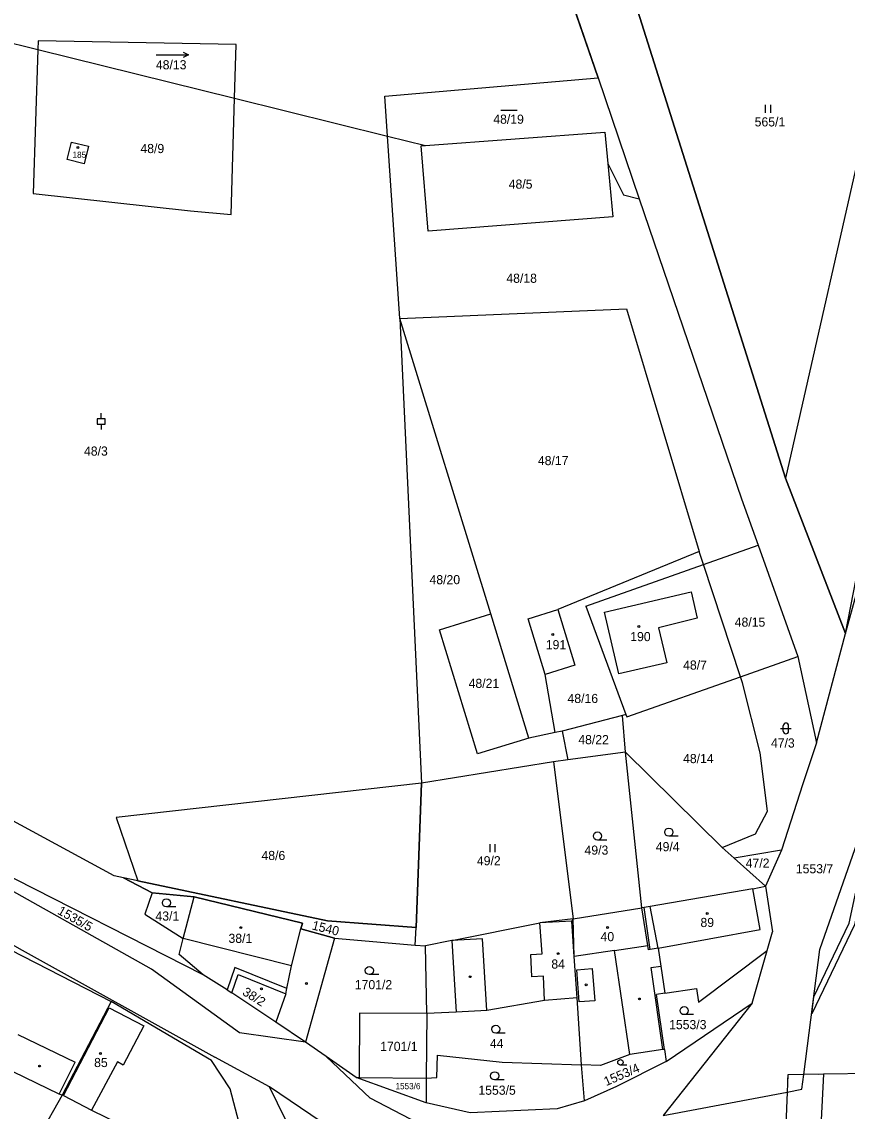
# Model space of a CAD drawing. Extents: x -801826 to -800592, y -1032871 to -1031813.
# Drawn here: x -801124.4 to -800970.8, y -1032380.8 to -1032178.1 of the extents above; entities that cross this region are included whole.
import ezdxf

# ---------------------------------------------------------------- set-up
doc = ezdxf.new("R2010")
doc.units = 0
for name, color, linetype in [('Vrstva 1', 7, 'Continuous'), ('Vrstva 18', 7, 'Continuous'), ('Vrstva 19', 7, 'Continuous'), ('Vrstva 25', 7, 'Continuous'), ('Vrstva 26', 7, 'Continuous'), ('Vrstva 27', 7, 'Continuous'), ('Vrstva 4', 7, 'Continuous')]:
    doc.layers.add(name, color=color, linetype=linetype)

msp = doc.modelspace()

# ---------------------------------------------------------------- linework, layer by layer
at = {"layer": 'Vrstva 1'}
for p, q in [((-801013.92, -1032163.13), (-800982.29, -1032263)), ((-800982.29, -1032263), (-801013.92, -1032163.13)), ((-801017.21, -1032188.54), (-801025.45, -1032164.36)), ((-801025.45, -1032164.36), (-801017.21, -1032188.54)), ((-800962.57, -1032175.77), (-800982.29, -1032263)), ((-801137.55, -1032179.29), (-801121.44, -1032183.28)), ((-801121.44, -1032183.28), (-801122.3, -1032210.08)), ((-801121.39, -1032181.67), (-801121.44, -1032183.28)), ((-801121.44, -1032183.28), (-801084.84, -1032192.36)), ((-801084.53, -1032182.36), (-801121.39, -1032181.67)), ((-801084.84, -1032192.36), (-801084.53, -1032182.36)), ((-800971.16, -1032291.94), (-800949.8, -1032181.86)), ((-801056.9, -1032191.96), (-801017.21, -1032188.54)), ((-801017.21, -1032188.54), (-801009.54, -1032211.04)), ((-801017.21, -1032188.54), (-801009.54, -1032211.04)), ((-801085.5, -1032214.01), (-801084.84, -1032192.36)), ((-801084.84, -1032192.36), (-801056.39, -1032199.42)), ((-801056.39, -1032199.42), (-801056.9, -1032191.96)), ((-801056.39, -1032199.42), (-801049.32, -1032201.17)), ((-801054.08, -1032233.3), (-801056.39, -1032199.42)), ((-801049.32, -1032201.17), (-801015.96, -1032198.66)), ((-801015.96, -1032198.66), (-801015.4, -1032204.5)), ((-801115.98, -1032203.74), (-801115.19, -1032200.51)), ((-801115.19, -1032200.51), (-801112.05, -1032201.3)), ((-801112.05, -1032201.3), (-801112.85, -1032204.53)), ((-801050.11, -1032201.23), (-801049.32, -1032201.17)), ((-801048.82, -1032217.11), (-801050.11, -1032201.23)), ((-801112.85, -1032204.53), (-801115.98, -1032203.74)), ((-801015.4, -1032204.5), (-801014.44, -1032214.44)), ((-801015.4, -1032204.5), (-801012.5, -1032210.33)), ((-801122.3, -1032210.08), (-801093.06, -1032213.29)), ((-801012.5, -1032210.33), (-801009.54, -1032211.04)), ((-801009.54, -1032211.04), (-800990.52, -1032266.86)), ((-801009.54, -1032211.04), (-800990.52, -1032266.86)), ((-801093.06, -1032213.29), (-801085.5, -1032214.01)), ((-801014.44, -1032214.44), (-801048.82, -1032217.11)), ((-801054.08, -1032233.3), (-801011.88, -1032231.52)), ((-801011.88, -1032231.52), (-800998.39, -1032276.7)), ((-801037.18, -1032288.28), (-801054.08, -1032233.3)), ((-801054.08, -1032233.3), (-801050.04, -1032319.76)), ((-800971.16, -1032291.94), (-800962.88, -1032261.83)), ((-800982.29, -1032263), (-800971.16, -1032291.94)), ((-800971.16, -1032291.94), (-800982.29, -1032263)), ((-800990.52, -1032266.86), (-800987.43, -1032275.48)), ((-800990.52, -1032266.86), (-800987.43, -1032275.48)), ((-800998.39, -1032276.7), (-801024.68, -1032287.48)), ((-800997.6, -1032279.08), (-800998.39, -1032276.7)), ((-800997.6, -1032279.08), (-800987.43, -1032275.48)), ((-800987.43, -1032275.48), (-800980, -1032296.19)), ((-800987.43, -1032275.48), (-800980, -1032296.19)), ((-801019.47, -1032286.83), (-800997.6, -1032279.08)), ((-800990.69, -1032299.97), (-800997.6, -1032279.08)), ((-801016.02, -1032287.95), (-800999.9, -1032284.18)), ((-800999.9, -1032284.18), (-800998.75, -1032289.09)), ((-801019.47, -1032286.83), (-801012.02, -1032307.02)), ((-801046.72, -1032291.22), (-801037.18, -1032288.28)), ((-801030.07, -1032311.4), (-801037.18, -1032288.28)), ((-801030.24, -1032289.17), (-801024.68, -1032287.48)), ((-801024.68, -1032287.48), (-801021.55, -1032297.82)), ((-801013.33, -1032299.43), (-801016.02, -1032287.95)), ((-801027.03, -1032299.56), (-801030.24, -1032289.17)), ((-800998.75, -1032289.09), (-801005.96, -1032290.88)), ((-801005.96, -1032290.88), (-801004.43, -1032297.4)), ((-801039.62, -1032314.34), (-801046.72, -1032291.22)), ((-800976.55, -1032312.27), (-800971.16, -1032291.94)), ((-800976.55, -1032312.27), (-800971.16, -1032291.94)), ((-800990.69, -1032299.97), (-800980, -1032296.19)), ((-800980, -1032296.19), (-800976.55, -1032312.27)), ((-800980, -1032296.19), (-800976.55, -1032312.27)), ((-801021.55, -1032297.82), (-801027.03, -1032299.56)), ((-801004.43, -1032297.4), (-801013.33, -1032299.43)), ((-801025.17, -1032310.34), (-801027.03, -1032299.56)), ((-801011.85, -1032307.45), (-800990.69, -1032299.97)), ((-800990.31, -1032301.13), (-800990.69, -1032299.97)), ((-800987.03, -1032314.12), (-800990.31, -1032301.13)), ((-801012.02, -1032307.02), (-801012.66, -1032307.19)), ((-801012.02, -1032307.02), (-801011.85, -1032307.45)), ((-801012.66, -1032307.19), (-801023.91, -1032310.07)), ((-801012.07, -1032314.03), (-801012.66, -1032307.19)), ((-801025.17, -1032310.34), (-801030.07, -1032311.4)), ((-801023.91, -1032310.07), (-801025.17, -1032310.34)), ((-801023.91, -1032310.07), (-801022.81, -1032315.43)), ((-801107.26, -1032337.02), (-801154.2, -1032311.57)), ((-801030.07, -1032311.4), (-801039.62, -1032314.34)), ((-800976.55, -1032312.27), (-800979.08, -1032319.89)), ((-801012.07, -1032314.03), (-801022.81, -1032315.43)), ((-800994.1, -1032331.73), (-801012.07, -1032314.03)), ((-801009.04, -1032342.97), (-801012.07, -1032314.03)), ((-800985.64, -1032324.97), (-800987.03, -1032314.12)), ((-801025.49, -1032315.78), (-801050.04, -1032319.76)), ((-801022.81, -1032315.43), (-801025.49, -1032315.78)), ((-801025.49, -1032315.78), (-801021.83, -1032344.98)), ((-801090.72, -1032355.44), (-801158.69, -1032320.84)), ((-801050.04, -1032319.76), (-801106.91, -1032326.16)), ((-801050.04, -1032319.76), (-801106.91, -1032326.16)), ((-801050.04, -1032319.76), (-801051.08, -1032346.63)), ((-801051.08, -1032346.63), (-801050.04, -1032319.76)), ((-800979.08, -1032319.89), (-800983.07, -1032332.22)), ((-801100.28, -1032354.34), (-801156.42, -1032323.04)), ((-800987.89, -1032329.2), (-800985.64, -1032324.97)), ((-801106.91, -1032326.16), (-801102.87, -1032337.94)), ((-801106.91, -1032326.16), (-801102.87, -1032337.94)), ((-800975.92, -1032350.71), (-800967.6, -1032326.98)), ((-800994.1, -1032331.73), (-800987.89, -1032329.2)), ((-801156.86, -1032332.67), (-801124.35, -1032350.83)), ((-800994.1, -1032331.73), (-800991.87, -1032333.72)), ((-800983.07, -1032332.22), (-800991.87, -1032333.72)), ((-800983.07, -1032332.22), (-800986.02, -1032338.94)), ((-800991.87, -1032333.72), (-800986.02, -1032338.94)), ((-801105.53, -1032337.38), (-801107.26, -1032337.02)), ((-801102.87, -1032337.94), (-801105.53, -1032337.38)), ((-801100.21, -1032340.16), (-801105.53, -1032337.38)), ((-801102.87, -1032337.94), (-801105.53, -1032337.38)), ((-801105.53, -1032337.38), (-801100.21, -1032340.16)), ((-801067.58, -1032345.38), (-801102.87, -1032337.94)), ((-801102.87, -1032337.94), (-801067.58, -1032345.38)), ((-801067.58, -1032345.38), (-801102.87, -1032337.94)), ((-800988.43, -1032339.45), (-801007.51, -1032342.71)), ((-800988.43, -1032339.45), (-800986.02, -1032338.94)), ((-800986.02, -1032338.94), (-800984.74, -1032347.41)), ((-801100.21, -1032340.16), (-801101.56, -1032344.12)), ((-801092.35, -1032340.92), (-801100.21, -1032340.16)), ((-801100.21, -1032340.16), (-801092.35, -1032340.92)), ((-801094.39, -1032348.66), (-801092.35, -1032340.92)), ((-801072.22, -1032345.8), (-801092.35, -1032340.92)), ((-801092.35, -1032340.92), (-801072.22, -1032345.8)), ((-801021.83, -1032344.98), (-801009.04, -1032342.97)), ((-801008.64, -1032342.91), (-801009.04, -1032342.97)), ((-801007.51, -1032342.71), (-801008.64, -1032342.91)), ((-801007.52, -1032350.72), (-801008.64, -1032342.91)), ((-801101.56, -1032344.12), (-801094.39, -1032348.66)), ((-801051.08, -1032346.63), (-801067.58, -1032345.38)), ((-801067.58, -1032345.38), (-801051.08, -1032346.63)), ((-801051.08, -1032346.63), (-801067.58, -1032345.38)), ((-801021.83, -1032344.98), (-801028.02, -1032345.75)), ((-801022.11, -1032345.46), (-801021.83, -1032344.98)), ((-801021.64, -1032352.01), (-801022.11, -1032345.46)), ((-801072.52, -1032346.86), (-801072.22, -1032345.8)), ((-801072.22, -1032345.8), (-801072.52, -1032346.86)), ((-801066.26, -1032348.61), (-801072.52, -1032346.86)), ((-801072.52, -1032346.86), (-801066.26, -1032348.61)), ((-801051.21, -1032349.89), (-801051.08, -1032346.63)), ((-801051.21, -1032349.89), (-801051.08, -1032346.63)), ((-801044.4, -1032349.06), (-801028.02, -1032345.75)), ((-800985.74, -1032350.88), (-800984.74, -1032347.41)), ((-801131.91, -1032348.04), (-801107.8, -1032360.39)), ((-801095.18, -1032351.66), (-801094.39, -1032348.66)), ((-801066.26, -1032348.61), (-801071.67, -1032367.94)), ((-801066.26, -1032348.61), (-801051.21, -1032349.89)), ((-801066.26, -1032348.61), (-801051.21, -1032349.89)), ((-801044.4, -1032349.06), (-801049.3, -1032350.05)), ((-801124.35, -1032350.83), (-801088.51, -1032370.73)), ((-801090.72, -1032355.44), (-801095.18, -1032351.66)), ((-801051.21, -1032349.89), (-801049.3, -1032350.05)), ((-801049.09, -1032362.64), (-801049.3, -1032350.05)), ((-801006.04, -1032350.45), (-801007.52, -1032350.72)), ((-801006.04, -1032350.45), (-801005.53, -1032353.78)), ((-800998.5, -1032360.53), (-800985.74, -1032350.88)), ((-800988.54, -1032360.72), (-800985.74, -1032350.88)), ((-800978.9, -1032373.98), (-800975.92, -1032350.71)), ((-801021.08, -1032359.72), (-801021.64, -1032352.01)), ((-801005.53, -1032353.78), (-801004.75, -1032358.85)), ((-801083.91, -1032366.23), (-801100.28, -1032354.34)), ((-801086.23, -1032358.24), (-801090.72, -1032355.44)), ((-801084.78, -1032354.07), (-801086.23, -1032358.24)), ((-801075.14, -1032357.96), (-801084.78, -1032354.07)), ((-801086.23, -1032358.24), (-801085.38, -1032358.78)), ((-801077.2, -1032364.24), (-801085.38, -1032358.78)), ((-801075.31, -1032358.95), (-801077.2, -1032364.24)), ((-801075.31, -1032358.95), (-801075.14, -1032357.96)), ((-801021.08, -1032359.72), (-801027.16, -1032360.2)), ((-801020.27, -1032372.17), (-801021.08, -1032359.72)), ((-801004.75, -1032358.85), (-801006.32, -1032359.09)), ((-801004.85, -1032369.3), (-801006.32, -1032359.09)), ((-801004.75, -1032358.85), (-800998.87, -1032357.96)), ((-800998.87, -1032357.96), (-800998.5, -1032360.53)), ((-801107.8, -1032360.39), (-801116.96, -1032377.78)), ((-801089.14, -1032371.37), (-801107.8, -1032360.39)), ((-801027.16, -1032360.2), (-801037.91, -1032362.04)), ((-800988.54, -1032360.72), (-801005.11, -1032381.61)), ((-801004.53, -1032371.53), (-800988.54, -1032360.72)), ((-801061.59, -1032362.54), (-801061.68, -1032374.54)), ((-801049.09, -1032362.64), (-801061.59, -1032362.54)), ((-801049.09, -1032362.64), (-801049.18, -1032374.64)), ((-801043.6, -1032362.38), (-801049.09, -1032362.64)), ((-801037.91, -1032362.04), (-801043.6, -1032362.38)), ((-801071.67, -1032367.94), (-801077.2, -1032364.24)), ((-801071.67, -1032367.94), (-801083.91, -1032366.23)), ((-801067.79, -1032370.64), (-801071.67, -1032367.94)), ((-801005.15, -1032369.34), (-801011.28, -1032370.25)), ((-801004.85, -1032369.3), (-801005.15, -1032369.34)), ((-801004.85, -1032369.3), (-801004.53, -1032371.53)), ((-801085.69, -1032376.62), (-801089.14, -1032371.37)), ((-801078.35, -1032376.25), (-801088.51, -1032370.73)), ((-801062.22, -1032374.52), (-801067.79, -1032370.64)), ((-801059.61, -1032378.37), (-801067.79, -1032370.64)), ((-801047.18, -1032374.54), (-801047.08, -1032370.36)), ((-801047.08, -1032370.36), (-801035.07, -1032371.66)), ((-801035.07, -1032371.66), (-801020.27, -1032372.17)), ((-801011.28, -1032370.25), (-801016.75, -1032372.29)), ((-801004.53, -1032371.53), (-801013.78, -1032376.2)), ((-801117.49, -1032377.59), (-801128.07, -1032372.48)), ((-801019.72, -1032378.86), (-801020.27, -1032372.17)), ((-801016.75, -1032372.29), (-801020.27, -1032372.17)), ((-800979.26, -1032376.69), (-800978.9, -1032373.98)), ((-800975.27, -1032373.92), (-800978.9, -1032373.98)), ((-800945.84, -1032373.44), (-800975.27, -1032373.92)), ((-801049.22, -1032379.24), (-801062.22, -1032374.52)), ((-801062.22, -1032374.52), (-801061.68, -1032374.54)), ((-801061.68, -1032374.54), (-801049.18, -1032374.64)), ((-801049.18, -1032374.64), (-801049.22, -1032379.24)), ((-801049.18, -1032374.64), (-801047.18, -1032374.54)), ((-801116.96, -1032377.78), (-801126.31, -1032394.49)), ((-801116.96, -1032377.78), (-801117.49, -1032377.59)), ((-801116.7, -1032377.88), (-801116.96, -1032377.78)), ((-801116.7, -1032377.88), (-801111.48, -1032380.61)), ((-801082.53, -1032388.65), (-801085.69, -1032376.62)), ((-801061.11, -1032387.87), (-801078.35, -1032376.25)), ((-801072.24, -1032388.64), (-801078.35, -1032376.25)), ((-801013.78, -1032376.2), (-801019.72, -1032378.86)), ((-801005.11, -1032381.61), (-800982.02, -1032377.22)), ((-800982.02, -1032377.22), (-800979.26, -1032376.69)), ((-801043.92, -1032386.49), (-801059.61, -1032378.37)), ((-801041, -1032381.1), (-801049.22, -1032379.24)), ((-801019.72, -1032378.86), (-801024.79, -1032380.35)), ((-801111.48, -1032380.61), (-801105.99, -1032383.29)), ((-801024.79, -1032380.35), (-801041, -1032381.1))]:
    msp.add_line(p, q, dxfattribs=at)
at = {"layer": 'Vrstva 25'}
for p, q in [((-801099.42, -1032184.3), (-801093.42, -1032184.3)), ((-800986.11, -1032193.6), (-800986.11, -1032195.1)), ((-800985.08, -1032195.1), (-800985.08, -1032193.6)), ((-801035.28, -1032194.58), (-801032.28, -1032194.58)), ((-801109.68, -1032251.97), (-801109.68, -1032250.97)), ((-801109.68, -1032252.97), (-801109.68, -1032253.97)), ((-800982.74, -1032310.09), (-800982.74, -1032309.09)), ((-800981.74, -1032310.09), (-800981.74, -1032309.09)), ((-800983.24, -1032309.59), (-800981.24, -1032309.59)), ((-801037.37, -1032331.09), (-801037.37, -1032332.59)), ((-801036.34, -1032332.59), (-801036.34, -1032331.09)), ((-801015.57, -1032330.35), (-801017.32, -1032330.35)), ((-801002.28, -1032329.63), (-801004.03, -1032329.63)), ((-801095.78, -1032342.78), (-801097.53, -1032342.78)), ((-801058.02, -1032355.37), (-801059.77, -1032355.37)), ((-800999.44, -1032362.83), (-801001.19, -1032362.83)), ((-801034.49, -1032366.29), (-801036.24, -1032366.29)), ((-801011.87, -1032372.2), (-801013.04, -1032372.2)), ((-801034.7, -1032374.96), (-801036.45, -1032374.96))]:
    msp.add_line(p, q, dxfattribs=at)
msp.add_lwpolyline([(-801094.42, -1032183.8), (-801093.42, -1032184.3), (-801094.42, -1032184.8)], dxfattribs=at)
msp.add_lwpolyline([(-801110.43, -1032252.97), (-801108.93, -1032252.97), (-801108.93, -1032251.97), (-801110.43, -1032251.97)], close=True, dxfattribs=at)
for centre, radius in [((-801113.99, -1032201.53), 0.175), ((-801009.63, -1032290.61), 0.175), ((-801025.65, -1032292.12), 0.175), ((-801017.32, -1032329.6), 0.75), ((-801004.03, -1032328.88), 0.75), ((-801097.53, -1032342.03), 0.75), ((-800996.87, -1032344.03), 0.175), ((-801083.69, -1032346.64), 0.175), ((-801015.42, -1032346.62), 0.175), ((-801024.61, -1032351.48), 0.175), ((-801059.77, -1032354.62), 0.75), ((-801041.01, -1032355.77), 0.175), ((-801071.49, -1032357.04), 0.175), ((-801019.42, -1032357.3), 0.175), ((-801079.86, -1032358.03), 0.175), ((-801009.52, -1032359.91), 0.175), ((-801001.19, -1032362.08), 0.75), ((-801036.24, -1032365.54), 0.75), ((-801109.83, -1032370.07), 0.175), ((-801013.04, -1032371.7), 0.503), ((-801121.13, -1032372.38), 0.175), ((-801036.45, -1032374.21), 0.75)]:
    msp.add_circle(centre, radius, dxfattribs=at)
for centre, start, end in [((-800982.24, -1032309.09), 0, 180), ((-800982.24, -1032310.09), 180, 0)]:
    msp.add_arc(centre, 0.5, start, end, dxfattribs=at)
at = {"layer": 'Vrstva 26'}
for p, q in [((-800981.9, -1032374.03), (-800981.94, -1032375.03)), ((-800975.27, -1032373.92), (-800976.27, -1032373.94))]:
    msp.add_line(p, q, dxfattribs=at)
at = {"layer": 'Vrstva 27'}
msp.add_lwpolyline([(-800970.45, -1032345.79), (-800963.99, -1032315.79), (-800963.02, -1032316.04), (-800969.49, -1032346.11), (-800977.45, -1032362.66), (-800977.05, -1032359.51), (-800970.45, -1032345.79)], dxfattribs=at)
at = {"layer": 'Vrstva 4'}
for p, q in [((-800987.02, -1032346.96), (-800988.43, -1032339.45)), ((-801007.91, -1032349.96), (-801009.04, -1032342.97)), ((-801006.04, -1032350.45), (-801007.51, -1032342.71)), ((-801022.11, -1032345.46), (-801028.02, -1032345.75)), ((-801021.64, -1032352.01), (-801021.83, -1032344.98)), ((-801074.28, -1032353.73), (-801072.52, -1032346.86)), ((-801027.59, -1032351.52), (-801028.02, -1032345.75)), ((-801006.04, -1032350.45), (-800987.02, -1032346.96)), ((-801074.28, -1032353.73), (-801094.39, -1032348.66)), ((-801038.71, -1032348.72), (-801044.4, -1032349.06)), ((-801044.4, -1032349.06), (-801043.6, -1032362.38)), ((-801037.91, -1032362.04), (-801038.71, -1032348.72)), ((-801029.7, -1032351.65), (-801027.59, -1032351.52)), ((-801029.53, -1032355.82), (-801029.7, -1032351.65)), ((-801014.14, -1032350.9), (-801021.64, -1032352.01)), ((-801014.14, -1032350.9), (-801007.91, -1032349.96)), ((-801011.28, -1032370.25), (-801014.14, -1032350.9)), ((-801007.79, -1032350.77), (-801007.91, -1032349.96)), ((-801007.52, -1032350.72), (-801007.79, -1032350.77)), ((-801075.14, -1032357.96), (-801074.28, -1032353.73)), ((-801007.32, -1032354.07), (-801005.53, -1032353.78)), ((-801085.38, -1032358.78), (-801084.16, -1032355.37)), ((-801084.16, -1032355.37), (-801075.31, -1032358.95)), ((-801027.38, -1032355.68), (-801029.53, -1032355.82)), ((-801027.16, -1032360.2), (-801027.38, -1032355.68)), ((-801021.16, -1032354.48), (-801018.27, -1032354.27)), ((-801020.72, -1032360.47), (-801021.16, -1032354.48)), ((-801018.27, -1032354.27), (-801017.83, -1032360.26)), ((-801005.15, -1032369.34), (-801007.32, -1032354.07)), ((-801116.7, -1032377.88), (-801108.16, -1032361.53)), ((-801108.16, -1032361.53), (-801101.74, -1032364.89)), ((-801017.83, -1032360.26), (-801020.72, -1032360.47)), ((-801101.74, -1032364.89), (-801105.56, -1032372.2)), ((-801125.18, -1032366.49), (-801114.49, -1032371.64)), ((-801117.49, -1032377.59), (-801114.49, -1032371.64)), ((-801106.66, -1032371.62), (-801111.48, -1032380.61)), ((-801105.56, -1032372.2), (-801106.66, -1032371.62)), ((-800981.9, -1032374.03), (-800982.02, -1032377.22)), ((-800978.9, -1032373.98), (-800981.9, -1032374.03)), ((-800975.27, -1032373.92), (-800975.67, -1032382.37)), ((-800982.02, -1032377.22), (-800982.25, -1032383.32))]:
    msp.add_line(p, q, dxfattribs=at)

# ---------------------------------------------------------------- texts
at = {"layer": 'Vrstva 18'}
for s, height, p in [('48/13', 1.7, (-801099.49, -1032186.98)), ('48/19', 1.7, (-801036.7, -1032197.1)), ('565/1', 1.7, (-800988.06, -1032197.6)), ('48/9', 1.7, (-801102.37, -1032202.56)), ('48/5', 1.7, (-801033.83, -1032209.18)), ('48/18', 1.7, (-801034.27, -1032226.69)), ('48/3', 1.7, (-801112.87, -1032258.84)), ('48/17', 1.7, (-801028.4, -1032260.61)), ('48/20', 1.7, (-801048.57, -1032282.76)), ('48/15', 1.7, (-800991.77, -1032290.66)), ('48/7', 1.7, (-801001.37, -1032298.65)), ('48/21', 1.7, (-801041.29, -1032302.05)), ('48/16', 1.7, (-801022.89, -1032304.86)), ('48/22', 1.7, (-801020.88, -1032312.52)), ('47/3', 1.7, (-800985.03, -1032313.14)), ('48/14', 1.7, (-801001.38, -1032316.04)), ('49/3', 1.7, (-801019.72, -1032333.07)), ('49/4', 1.7, (-801006.45, -1032332.43)), ('48/6', 1.7, (-801079.84, -1032334.07)), ('49/2', 1.7, (-801039.75, -1032335.05)), ('47/2', 1.7, (-800989.73, -1032335.49)), ('1553/7', 1.7, (-800980.4, -1032336.54)), ('43/1', 1.7, (-801099.57, -1032345.33)), ('1701/2', 1.7, (-801062.47, -1032358.09)), ('1553/3', 1.7, (-801003.98, -1032365.53)), ('1701/1', 1.7, (-801057.75, -1032369.58)), ('44', 1.7, (-801037.33, -1032369.04)), ('1553/6', 1.14, (-801054.91, -1032376.7)), ('1553/5', 1.7, (-801039.47, -1032377.73))]:
    msp.add_text(s, height=height, dxfattribs=at).set_placement(p)
for s, rotation, p in [('1535/5', 330.672, (-801117.94, -1032344)), ('1540', 346.2299, (-801070.55, -1032346.96)), ('1553/4', 23.297, (-801015.68, -1032376.13))]:
    msp.add_text(s, height=1.7, rotation=rotation, dxfattribs=at).set_placement(p)
at = {"layer": 'Vrstva 19'}
for s, height, p in [('185', 1.14, (-801115.01, -1032203.44)), ('190', 1.7, (-801011.21, -1032293.35)), ('191', 1.7, (-801026.93, -1032294.86)), ('89', 1.7, (-800998.15, -1032346.53)), ('38/1', 1.7, (-801085.98, -1032349.48)), ('40', 1.7, (-801016.74, -1032349.16)), ('84', 1.7, (-801025.9, -1032354.26)), ('85', 1.7, (-801110.99, -1032372.58))]:
    msp.add_text(s, height=height, dxfattribs=at).set_placement(p)
msp.add_text('38/2', height=1.7, rotation=327.8419, dxfattribs=at).set_placement((-801083.53, -1032359.04))

doc.saveas('drawing.dxf')
